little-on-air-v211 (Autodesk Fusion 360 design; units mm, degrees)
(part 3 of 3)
sketch "Broad XIAO short-end contact profile (3)" plane through (0, 0, -12.35) normal (0, 0, 1) x axis (1, 0, 0)
  line L1 (106.8, 55.8) -> (104.3, 55.8)
  line L2 (106.8, 58.2) -> (106.8, 55.8)
  line L3 (104.3, 58.2) -> (106.8, 58.2)
  line L4 (104.3, 55.8) -> (104.3, 58.2)
  point P2 (104.3, 55.8)
  point P3 (106.8, 55.8)
  point P4 (106.8, 58.2)
  dimension "d911" distance P2 P3 = 2.5
  dimension "d912" distance P3 P4 = 2.4
extrude "Extrude50" new body sketch "Broad XIAO short-end contact profile (3)" against normal blind 5.9 bodies "Broad XIAO short-end contact (3)"
combine "Combine3" bodies "Broad XIAO short-end contact", "Broad XIAO short-end contact (1)", "Broad XIAO short-end contact (2)", "Broad XIAO short-end contact (3)"
work_plane "WorkPlane51" AlongDistance -9.63 ExtraOffset 0
sketch "Reopen RGB sight through wide upper pad root profile" plane through (0, 0, -9.63) normal (0, 0, 1) x axis (1, 0, 0)
  circle C1 centre (103.605, 55.006) radius 1.6
  dimension "d917" diameter C1 = 3.2
extrude "Extrude51" cut sketch "Reopen RGB sight through wide upper pad root profile" against normal blind 8.9
work_plane "WorkPlane84" AlongDistance -9.48 ExtraOffset 0
sketch "Both MODE terminal rows load without a comb profile" plane through (0, 0, -9.48) normal (0, 0, 1) x axis (1, 0, 0)
  line L1 (63.1, 53.64) -> (56.9, 53.64)
  line L2 (63.1, 55.29) -> (63.1, 53.64)
  line L3 (56.9, 55.29) -> (63.1, 55.29)
  line L4 (56.9, 53.64) -> (56.9, 55.29)
  point P2 (56.9, 53.64)
  point P3 (63.1, 53.64)
  point P4 (63.1, 55.29)
  dimension "d922" distance P2 P3 = 6.2
  dimension "d923" distance P3 P4 = 1.65
extrude "Extrude84" cut sketch "Both MODE terminal rows load without a comb profile" against normal blind 8.57
work_plane "WorkPlane85" AlongDistance -9.48 ExtraOffset 0
sketch "POWER solder pins load from open front profile" plane through (0, 0, -9.48) normal (0, 0, 1) x axis (1, 0, 0)
  line L1 (46.1, 48.25) -> (35.9, 48.25)
  line L2 (46.1, 53.35) -> (46.1, 48.25)
  line L3 (35.9, 53.35) -> (46.1, 53.35)
  line L4 (35.9, 48.25) -> (35.9, 53.35)
  point P2 (35.9, 48.25)
  point P3 (46.1, 48.25)
  point P4 (46.1, 53.35)
  dimension "d928" distance P2 P3 = 10.2
  dimension "d929" distance P3 P4 = 5.1
extrude "Extrude85" cut sketch "POWER solder pins load from open front profile" against normal blind 11.02
work_plane "WorkPlane86" AlongDistance -9.48 ExtraOffset 0
sketch "XIAO keeper upper rail pocket profile" plane through (0, 0, -9.48) normal (0, 0, 1) x axis (1, 0, 0)
  line L1 (109.75, 57.35) -> (86.25, 57.35)
  line L2 (109.75, 58.05) -> (109.75, 57.35)
  line L3 (86.25, 58.05) -> (109.75, 58.05)
  line L4 (86.25, 57.35) -> (86.25, 58.05)
  point P2 (86.25, 57.35)
  point P3 (109.75, 57.35)
  point P4 (109.75, 58.05)
  dimension "d934" distance P2 P3 = 23.5
  dimension "d935" distance P3 P4 = 0.7
extrude "Extrude86" cut sketch "XIAO keeper upper rail pocket profile" against normal blind 3.17
work_plane "WorkPlane52" AlongDistance -9.63 ExtraOffset 0
sketch "Keeper clears upper-left closure boss profile" plane through (0, 0, -9.63) normal (0, 0, 1) x axis (1, 0, 0)
  line L1 (10.45, 49.55) -> (9.9, 49.55)
  line L2 (10.45, 58.45) -> (10.45, 49.55)
  line L3 (9.9, 58.45) -> (10.45, 58.45)
  line L4 (9.9, 49.55) -> (9.9, 58.45)
  point P2 (9.9, 49.55)
  point P3 (10.45, 49.55)
  point P4 (10.45, 58.45)
  dimension "d940" distance P2 P3 = 0.55
  dimension "d941" distance P3 P4 = 8.9
extrude "Extrude52" cut sketch "Keeper clears upper-left closure boss profile" against normal blind 5
work_plane "WorkPlane87" AlongDistance -9.48 ExtraOffset 0
sketch "Wide upper keeper landing clearance profile" plane through (0, 0, -9.48) normal (0, 0, 1) x axis (1, 0, 0)
  line L1 (91.05, 57.35) -> (88.15, 57.35)
  line L2 (91.05, 58.45) -> (91.05, 57.35)
  line L3 (88.15, 58.45) -> (91.05, 58.45)
  line L4 (88.15, 57.35) -> (88.15, 58.45)
  point P2 (88.15, 57.35)
  point P3 (91.05, 57.35)
  point P4 (91.05, 58.45)
  dimension "d946" distance P2 P3 = 2.9
  dimension "d947" distance P3 P4 = 1.1
extrude "Extrude87" cut sketch "Wide upper keeper landing clearance profile" against normal blind 9.02
work_plane "WorkPlane88" AlongDistance -9.48 ExtraOffset 0
sketch "Wide upper keeper landing clearance profile (1)" plane through (0, 0, -9.48) normal (0, 0, 1) x axis (1, 0, 0)
  line L1 (107.05, 57.35) -> (104.05, 57.35)
  line L2 (107.05, 58.45) -> (107.05, 57.35)
  line L3 (104.05, 58.45) -> (107.05, 58.45)
  line L4 (104.05, 57.35) -> (104.05, 58.45)
  point P2 (104.05, 57.35)
  point P3 (107.05, 57.35)
  point P4 (107.05, 58.45)
  dimension "d952" distance P2 P3 = 3
  dimension "d953" distance P3 P4 = 1.1
extrude "Extrude88" cut sketch "Wide upper keeper landing clearance profile (1)" against normal blind 9.02
work_plane "WorkPlane89" AlongDistance -9.48 ExtraOffset 0
sketch "Open POWER bracket ends without thin fins profile" plane through (0, 0, -9.48) normal (0, 0, 1) x axis (1, 0, 0)
  line L1 (51.11, 57.65) -> (30.89, 57.65)
  line L2 (51.11, 58.6) -> (51.11, 57.65)
  line L3 (30.89, 58.6) -> (51.11, 58.6)
  line L4 (30.89, 57.65) -> (30.89, 58.6)
  point P2 (30.89, 57.65)
  point P3 (51.11, 57.65)
  point P4 (51.11, 58.6)
  dimension "d958" distance P2 P3 = 20.22
  dimension "d959" distance P3 P4 = 0.95
extrude "Extrude89" cut sketch "Open POWER bracket ends without thin fins profile" against normal blind 10.77
work_plane "WorkPlane1" AlongDistance -6.6 ExtraOffset 0
sketch "Closure screw shaft profile" plane through (0, 0, -6.6) normal (0, 0, 1) x axis (1, 0, 0)
  circle C1 centre (6, 6) radius 1.5
  dimension "d964" diameter C1 = 3
extrude "Extrude1" new body sketch "Closure screw shaft profile" against normal blind 8 bodies "Closure screw shaft"
work_plane "WorkPlane2" AlongDistance -4.95 ExtraOffset 0
sketch "Closure screw head profile" plane through (0, 0, -4.95) normal (0, 0, 1) x axis (1, 0, 0)
  circle C1 centre (6, 6) radius 2.85
  dimension "d969" diameter C1 = 5.7
extrude "Extrude2" new body sketch "Closure screw head profile" against normal blind 1.65 bodies "Closure screw head"
work_plane "WorkPlane1" AlongDistance -11.6 ExtraOffset 0
sketch "Nut profile" plane through (0, 0, -11.6) normal (0, 0, 1) x axis (1, 0, 0)
  line L1 (7.5877, 8.75) -> (9.1754, 6)
  line L2 (4.4123, 8.75) -> (7.5877, 8.75)
  line L3 (2.8246, 6) -> (4.4123, 8.75)
  line L4 (4.4123, 3.25) -> (2.8246, 6)
  line L5 (7.5877, 3.25) -> (4.4123, 3.25)
  line L6 (9.1754, 6) -> (7.5877, 3.25)
extrude "Extrude1" new body sketch "Nut profile" against normal blind 2.4 bodies "M3 nut"
work_plane "WorkPlane2" AlongDistance -11.59 ExtraOffset 0
sketch "M3 threaded bore envelope profile" plane through (0, 0, -11.59) normal (0, 0, 1) x axis (1, 0, 0)
  circle C1 centre (6, 6) radius 1.505
  dimension "d978" diameter C1 = 3.01
extrude "Extrude2" cut sketch "M3 threaded bore envelope profile" against normal blind 2.42
work_plane "WorkPlane3" AlongDistance -6.6 ExtraOffset 0
sketch "Closure screw shaft profile (1)" plane through (0, 0, -6.6) normal (0, 0, 1) x axis (1, 0, 0)
  circle C1 centre (114, 6) radius 1.5
  dimension "d983" diameter C1 = 3
extrude "Extrude3" new body sketch "Closure screw shaft profile (1)" against normal blind 8 bodies "Closure screw shaft (1)"
work_plane "WorkPlane4" AlongDistance -4.95 ExtraOffset 0
sketch "Closure screw head profile (1)" plane through (0, 0, -4.95) normal (0, 0, 1) x axis (1, 0, 0)
  circle C1 centre (114, 6) radius 2.85
  dimension "d988" diameter C1 = 5.7
extrude "Extrude4" new body sketch "Closure screw head profile (1)" against normal blind 1.65 bodies "Closure screw head (1)"
work_plane "WorkPlane3" AlongDistance -11.6 ExtraOffset 0
sketch "Nut profile (1)" plane through (0, 0, -11.6) normal (0, 0, 1) x axis (1, 0, 0)
  line L1 (115.5877, 8.75) -> (117.1754, 6)
  line L2 (112.4123, 8.75) -> (115.5877, 8.75)
  line L3 (110.8246, 6) -> (112.4123, 8.75)
  line L4 (112.4123, 3.25) -> (110.8246, 6)
  line L5 (115.5877, 3.25) -> (112.4123, 3.25)
  line L6 (117.1754, 6) -> (115.5877, 3.25)
extrude "Extrude3" new body sketch "Nut profile (1)" against normal blind 2.4 bodies "M3 nut (1)"
work_plane "WorkPlane4" AlongDistance -11.59 ExtraOffset 0
sketch "M3 threaded bore envelope profile (1)" plane through (0, 0, -11.59) normal (0, 0, 1) x axis (1, 0, 0)
  circle C1 centre (114, 6) radius 1.505
  dimension "d997" diameter C1 = 3.01
extrude "Extrude4" cut sketch "M3 threaded bore envelope profile (1)" against normal blind 2.42
work_plane "WorkPlane5" AlongDistance -6.6 ExtraOffset 0
sketch "Closure screw shaft profile (2)" plane through (0, 0, -6.6) normal (0, 0, 1) x axis (1, 0, 0)
  circle C1 centre (6, 54) radius 1.5
  dimension "d1002" diameter C1 = 3
extrude "Extrude5" new body sketch "Closure screw shaft profile (2)" against normal blind 8 bodies "Closure screw shaft (2)"
work_plane "WorkPlane6" AlongDistance -4.95 ExtraOffset 0
sketch "Closure screw head profile (2)" plane through (0, 0, -4.95) normal (0, 0, 1) x axis (1, 0, 0)
  circle C1 centre (6, 54) radius 2.85
  dimension "d1007" diameter C1 = 5.7
extrude "Extrude6" new body sketch "Closure screw head profile (2)" against normal blind 1.65 bodies "Closure screw head (2)"
work_plane "WorkPlane5" AlongDistance -11.6 ExtraOffset 0
sketch "Nut profile (2)" plane through (0, 0, -11.6) normal (0, 0, 1) x axis (1, 0, 0)
  line L1 (3.25, 55.5877) -> (6, 57.1754)
  line L2 (3.25, 52.4123) -> (3.25, 55.5877)
  line L3 (6, 50.8246) -> (3.25, 52.4123)
  line L4 (8.75, 52.4123) -> (6, 50.8246)
  line L5 (8.75, 55.5877) -> (8.75, 52.4123)
  line L6 (6, 57.1754) -> (8.75, 55.5877)
extrude "Extrude5" new body sketch "Nut profile (2)" against normal blind 2.4 bodies "M3 nut (2)"
work_plane "WorkPlane6" AlongDistance -11.59 ExtraOffset 0
sketch "M3 threaded bore envelope profile (2)" plane through (0, 0, -11.59) normal (0, 0, 1) x axis (1, 0, 0)
  circle C1 centre (6, 54) radius 1.505
  dimension "d1016" diameter C1 = 3.01
extrude "Extrude6" cut sketch "M3 threaded bore envelope profile (2)" against normal blind 2.42
work_plane "WorkPlane7" AlongDistance -6.6 ExtraOffset 0
sketch "Closure screw shaft profile (3)" plane through (0, 0, -6.6) normal (0, 0, 1) x axis (1, 0, 0)
  circle C1 centre (114, 54) radius 1.5
  dimension "d1021" diameter C1 = 3
extrude "Extrude7" new body sketch "Closure screw shaft profile (3)" against normal blind 8 bodies "Closure screw shaft (3)"
work_plane "WorkPlane8" AlongDistance -4.95 ExtraOffset 0
sketch "Closure screw head profile (3)" plane through (0, 0, -4.95) normal (0, 0, 1) x axis (1, 0, 0)
  circle C1 centre (114, 54) radius 2.85
  dimension "d1026" diameter C1 = 5.7
extrude "Extrude8" new body sketch "Closure screw head profile (3)" against normal blind 1.65 bodies "Closure screw head (3)"
work_plane "WorkPlane7" AlongDistance -11.6 ExtraOffset 0
sketch "Nut profile (3)" plane through (0, 0, -11.6) normal (0, 0, 1) x axis (1, 0, 0)
  line L1 (115.5877, 56.75) -> (117.1754, 54)
  line L2 (112.4123, 56.75) -> (115.5877, 56.75)
  line L3 (110.8246, 54) -> (112.4123, 56.75)
  line L4 (112.4123, 51.25) -> (110.8246, 54)
  line L5 (115.5877, 51.25) -> (112.4123, 51.25)
  line L6 (117.1754, 54) -> (115.5877, 51.25)
extrude "Extrude7" new body sketch "Nut profile (3)" against normal blind 2.4 bodies "M3 nut (3)"
work_plane "WorkPlane8" AlongDistance -11.59 ExtraOffset 0
sketch "M3 threaded bore envelope profile (3)" plane through (0, 0, -11.59) normal (0, 0, 1) x axis (1, 0, 0)
  circle C1 centre (114, 54) radius 1.505
  dimension "d1035" diameter C1 = 3.01
extrude "Extrude8" cut sketch "M3 threaded bore envelope profile (3)" against normal blind 2.42
work_plane "WorkPlane9" AlongDistance -1.075 ExtraOffset 0
sketch "Optical screw shaft profile" plane through (0, 0, -1.075) normal (0, 0, 1) x axis (1, 0, 0)
  circle C1 centre (60, 6) radius 1.5
  dimension "d1040" diameter C1 = 3
extrude "Extrude9" new body sketch "Optical screw shaft profile" against normal blind 8 bodies "Optical screw shaft"
work_plane "WorkPlane10" AlongDistance -9.075 ExtraOffset 0
sketch "Optical screw head profile" plane through (0, 0, -9.075) normal (0, 0, 1) x axis (1, 0, 0)
  circle C1 centre (60, 6) radius 2.85
  dimension "d1045" diameter C1 = 5.7
extrude "Extrude10" new body sketch "Optical screw head profile" against normal blind 1.65 bodies "Optical screw head"
work_plane "WorkPlane9" AlongDistance -3.3 ExtraOffset 0
sketch "Nut profile (4)" plane through (0, 0, -3.3) normal (0, 0, 1) x axis (1, 0, 0)
  line L1 (61.5877, 8.75) -> (63.1754, 6)
  line L2 (58.4123, 8.75) -> (61.5877, 8.75)
  line L3 (56.8246, 6) -> (58.4123, 8.75)
  line L4 (58.4123, 3.25) -> (56.8246, 6)
  line L5 (61.5877, 3.25) -> (58.4123, 3.25)
  line L6 (63.1754, 6) -> (61.5877, 3.25)
extrude "Extrude9" new body sketch "Nut profile (4)" against normal blind 2.4 bodies "M3 nut (4)"
work_plane "WorkPlane10" AlongDistance -3.29 ExtraOffset 0
sketch "M3 threaded bore envelope profile (4)" plane through (0, 0, -3.29) normal (0, 0, 1) x axis (1, 0, 0)
  circle C1 centre (60, 6) radius 1.505
  dimension "d1054" diameter C1 = 3.01
extrude "Extrude10" cut sketch "M3 threaded bore envelope profile (4)" against normal blind 2.42
work_plane "WorkPlane11" AlongDistance -1.075 ExtraOffset 0
sketch "Optical screw shaft profile (1)" plane through (0, 0, -1.075) normal (0, 0, 1) x axis (1, 0, 0)
  circle C1 centre (60, 54) radius 1.5
  dimension "d1059" diameter C1 = 3
extrude "Extrude11" new body sketch "Optical screw shaft profile (1)" against normal blind 8 bodies "Optical screw shaft (1)"
work_plane "WorkPlane12" AlongDistance -9.075 ExtraOffset 0
sketch "Optical screw head profile (1)" plane through (0, 0, -9.075) normal (0, 0, 1) x axis (1, 0, 0)
  circle C1 centre (60, 54) radius 2.85
  dimension "d1064" diameter C1 = 5.7
extrude "Extrude12" new body sketch "Optical screw head profile (1)" against normal blind 1.65 bodies "Optical screw head (1)"
work_plane "WorkPlane11" AlongDistance -3.3 ExtraOffset 0
sketch "Nut profile (5)" plane through (0, 0, -3.3) normal (0, 0, 1) x axis (1, 0, 0)
  line L1 (61.5877, 56.75) -> (63.1754, 54)
  line L2 (58.4123, 56.75) -> (61.5877, 56.75)
  line L3 (56.8246, 54) -> (58.4123, 56.75)
  line L4 (58.4123, 51.25) -> (56.8246, 54)
  line L5 (61.5877, 51.25) -> (58.4123, 51.25)
  line L6 (63.1754, 54) -> (61.5877, 51.25)
extrude "Extrude11" new body sketch "Nut profile (5)" against normal blind 2.4 bodies "M3 nut (5)"
work_plane "WorkPlane12" AlongDistance -3.29 ExtraOffset 0
sketch "M3 threaded bore envelope profile (5)" plane through (0, 0, -3.29) normal (0, 0, 1) x axis (1, 0, 0)
  circle C1 centre (60, 54) radius 1.505
  dimension "d1073" diameter C1 = 3.01
extrude "Extrude12" cut sketch "M3 threaded bore envelope profile (5)" against normal blind 2.42
work_plane "WorkPlane13" AlongDistance -9.65 ExtraOffset 0
sketch "Keeper screw shaft profile" plane through (0, 0, -9.65) normal (0, 0, 1) x axis (1, 0, 0)
  circle C1 centre (35, 38) radius 1.5
  dimension "d1078" diameter C1 = 3
extrude "Extrude13" new body sketch "Keeper screw shaft profile" against normal blind 8 bodies "Keeper screw shaft"
work_plane "WorkPlane14" AlongDistance -8 ExtraOffset 0
sketch "Keeper screw head profile" plane through (0, 0, -8) normal (0, 0, 1) x axis (1, 0, 0)
  circle C1 centre (35, 38) radius 2.85
  dimension "d1083" diameter C1 = 5.7
extrude "Extrude14" new body sketch "Keeper screw head profile" against normal blind 1.65 bodies "Keeper screw head"
work_plane "WorkPlane13" AlongDistance -13.9 ExtraOffset 0
sketch "Nut profile (6)" plane through (0, 0, -13.9) normal (0, 0, 1) x axis (1, 0, 0)
  line L1 (36.5877, 40.75) -> (38.1754, 38)
  line L2 (33.4123, 40.75) -> (36.5877, 40.75)
  line L3 (31.8246, 38) -> (33.4123, 40.75)
  line L4 (33.4123, 35.25) -> (31.8246, 38)
  line L5 (36.5877, 35.25) -> (33.4123, 35.25)
  line L6 (38.1754, 38) -> (36.5877, 35.25)
extrude "Extrude13" new body sketch "Nut profile (6)" against normal blind 2.4 bodies "M3 nut (6)"
work_plane "WorkPlane14" AlongDistance -13.89 ExtraOffset 0
sketch "M3 threaded bore envelope profile (6)" plane through (0, 0, -13.89) normal (0, 0, 1) x axis (1, 0, 0)
  circle C1 centre (35, 38) radius 1.505
  dimension "d1092" diameter C1 = 3.01
extrude "Extrude14" cut sketch "M3 threaded bore envelope profile (6)" against normal blind 2.42
work_plane "WorkPlane15" AlongDistance -9.65 ExtraOffset 0
sketch "Keeper screw shaft profile (1)" plane through (0, 0, -9.65) normal (0, 0, 1) x axis (1, 0, 0)
  circle C1 centre (73, 38) radius 1.5
  dimension "d1097" diameter C1 = 3
extrude "Extrude15" new body sketch "Keeper screw shaft profile (1)" against normal blind 8 bodies "Keeper screw shaft (1)"
work_plane "WorkPlane16" AlongDistance -8 ExtraOffset 0
sketch "Keeper screw head profile (1)" plane through (0, 0, -8) normal (0, 0, 1) x axis (1, 0, 0)
  circle C1 centre (73, 38) radius 2.85
  dimension "d1102" diameter C1 = 5.7
extrude "Extrude16" new body sketch "Keeper screw head profile (1)" against normal blind 1.65 bodies "Keeper screw head (1)"
work_plane "WorkPlane15" AlongDistance -13.9 ExtraOffset 0
sketch "Nut profile (7)" plane through (0, 0, -13.9) normal (0, 0, 1) x axis (1, 0, 0)
  line L1 (74.5877, 40.75) -> (76.1754, 38)
  line L2 (71.4123, 40.75) -> (74.5877, 40.75)
  line L3 (69.8246, 38) -> (71.4123, 40.75)
  line L4 (71.4123, 35.25) -> (69.8246, 38)
  line L5 (74.5877, 35.25) -> (71.4123, 35.25)
  line L6 (76.1754, 38) -> (74.5877, 35.25)
extrude "Extrude15" new body sketch "Nut profile (7)" against normal blind 2.4 bodies "M3 nut (7)"
work_plane "WorkPlane16" AlongDistance -13.89 ExtraOffset 0
sketch "M3 threaded bore envelope profile (7)" plane through (0, 0, -13.89) normal (0, 0, 1) x axis (1, 0, 0)
  circle C1 centre (73, 38) radius 1.505
  dimension "d1111" diameter C1 = 3.01
extrude "Extrude16" cut sketch "M3 threaded bore envelope profile (7)" against normal blind 2.42
work_plane "WorkPlane53" AlongDistance -9.63 ExtraOffset 0
sketch "Optical head running pocket with thick roof profile" plane through (0, 0, -9.63) normal (0, 0, 1) x axis (1, 0, 0)
  circle C1 centre (60, 54) radius 3.2
  dimension "d1116" diameter C1 = 6.4
extrude "Extrude53" cut sketch "Optical head running pocket with thick roof profile" against normal blind 1.5
work_plane "WorkPlane90" AlongDistance -13.8 ExtraOffset 0
sketch "Keeper nut clears later charger fence" plane through (0, 0, -13.8) normal (0, 0, 1) x axis (1, 0, 0)
  line L1 (36.7321, 41) -> (38.4641, 38)
  line L2 (33.2679, 41) -> (36.7321, 41)
  line L3 (31.5359, 38) -> (33.2679, 41)
  line L4 (33.2679, 35) -> (31.5359, 38)
  line L5 (36.7321, 35) -> (33.2679, 35)
  line L6 (38.4641, 38) -> (36.7321, 35)
extrude "Extrude90" cut sketch "Keeper nut clears later charger fence" against normal blind 3
work_plane "WorkPlane91" AlongDistance -15 ExtraOffset 0
sketch "Full 17.5 mm charger lower edge stop profile" plane through (0, 0, -15) normal (0, 0, 1) x axis (1, 0, 0)
  line L1 (29.75, 28.1) -> (12.25, 28.1)
  line L2 (29.75, 30) -> (29.75, 28.1)
  line L3 (12.25, 30) -> (29.75, 30)
  line L4 (12.25, 28.1) -> (12.25, 30)
  point P2 (12.25, 28.1)
  point P3 (29.75, 28.1)
  point P4 (29.75, 30)
  dimension "d1125" distance P2 P3 = 17.5
  dimension "d1126" distance P3 P4 = 1.9
extrude "Extrude91" new body sketch "Full 17.5 mm charger lower edge stop profile" against normal blind 6.7 bodies "Full 17.5 mm charger lower edge stop"
combine "Combine8" bodies "Full 17.5 mm charger lower edge stop"
work_plane "WorkPlane1" AlongDistance 0.8 ExtraOffset 0
sketch "Optical shaft profile" plane through (0, 0, 0.8) normal (0, 0, 1) x axis (1, 0, 0)
  circle C1 centre (103.605, 55.006) radius 1.525
  dimension "d1132" diameter C1 = 3.05 (= "indicator_guide_diameter")
extrude "Extrude1" new body sketch "Optical shaft profile" against normal blind 15.5 bodies "Optical shaft"
work_plane "WorkPlane2" AlongDistance -14.65 ExtraOffset 0
sketch "Narrow 1.8 mm LED pickup clears USB metal profile" plane through (0, 0, -14.65) normal (0, 0, 1) x axis (1, 0, 0)
  circle C1 centre (103.605, 55.006) radius 0.9
  dimension "d1137" diameter C1 = 1.8
extrude "Extrude2" new body sketch "Narrow 1.8 mm LED pickup clears USB metal profile" against normal blind 2.85 bodies "Narrow 1.8 mm LED pickup clears USB metal"
work_plane "WorkPlane3" AlongDistance 0.8 ExtraOffset 0
sketch "Insertion stop collar profile" plane through (0, 0, 0.8) normal (0, 0, 1) x axis (1, 0, 0)
  circle C1 centre (103.605, 55.006) radius 2.1
  dimension "d1142" diameter C1 = 4.2
extrude "Extrude3" new body sketch "Insertion stop collar profile" against normal blind 0.8 bodies "Insertion stop collar"
combine "Combine1" bodies "Narrow 1.8 mm LED pickup clears USB metal", "Insertion stop collar"
work_plane "WorkPlane4" AlongDistance 0.81 ExtraOffset 0
sketch "Continuous flat printing face profile" plane through (0, 0, 0.81) normal (0, 0, 1) x axis (1, 0, 0)
  line L1 (106.605, 51.006) -> (100.605, 51.006)
  line L2 (106.605, 54.306) -> (106.605, 51.006)
  line L3 (100.605, 54.306) -> (106.605, 54.306)
  line L4 (100.605, 51.006) -> (100.605, 54.306)
  point P2 (100.605, 51.006)
  point P3 (106.605, 51.006)
  point P4 (106.605, 54.306)
  dimension "d1147" distance P2 P3 = 6
  dimension "d1148" distance P3 P4 = 3.3
extrude "Extrude4" cut sketch "Continuous flat printing face profile" against normal blind 18.32
work_plane "WorkPlane1" AlongDistance -17.6 ExtraOffset 0
sketch "Optical shaft profile" plane through (0, 0, -17.6) normal (0, 0, 1) x axis (1, 0, 0)
  circle C1 centre (14, 49.4) radius 1.525
  dimension "d1153" diameter C1 = 3.05 (= "indicator_guide_diameter")
extrude "Extrude1" new body sketch "Optical shaft profile" against normal blind 6.3 bodies "Optical shaft"
work_plane "WorkPlane2" AlongDistance -20.5 ExtraOffset 0
sketch "Insertion stop collar profile" plane through (0, 0, -20.5) normal (0, 0, 1) x axis (1, 0, 0)
  circle C1 centre (14, 49.4) radius 2.1
  dimension "d1158" diameter C1 = 4.2
extrude "Extrude2" new body sketch "Insertion stop collar profile" against normal blind 1.2 bodies "Insertion stop collar"
combine "Combine1" bodies "Insertion stop collar"
work_plane "WorkPlane3" AlongDistance -17.59 ExtraOffset 0
sketch "Continuous flat printing face profile" plane through (0, 0, -17.59) normal (0, 0, 1) x axis (1, 0, 0)
  line L1 (17, 45.4) -> (11, 45.4)
  line L2 (17, 48.7) -> (17, 45.4)
  line L3 (11, 48.7) -> (17, 48.7)
  line L4 (11, 45.4) -> (11, 48.7)
  point P2 (11, 45.4)
  point P3 (17, 45.4)
  point P4 (17, 48.7)
  dimension "d1163" distance P2 P3 = 6
  dimension "d1164" distance P3 P4 = 3.3
extrude "Extrude3" cut sketch "Continuous flat printing face profile" against normal blind 6.32
work_plane "WorkPlane4" AlongDistance -17.59 ExtraOffset 0
sketch "Charger fence relief flat profile" plane through (0, 0, -17.59) normal (0, 0, 1) x axis (1, 0, 0)
  line L1 (12.2, 46.4) -> (11, 46.4)
  line L2 (12.2, 52.4) -> (12.2, 46.4)
  line L3 (11, 52.4) -> (12.2, 52.4)
  line L4 (11, 46.4) -> (11, 52.4)
  point P2 (11, 46.4)
  point P3 (12.2, 46.4)
  point P4 (12.2, 52.4)
  dimension "d1169" distance P2 P3 = 1.2
  dimension "d1170" distance P3 P4 = 6
extrude "Extrude4" cut sketch "Charger fence relief flat profile" against normal blind 6.32
work_plane "WorkPlane1" AlongDistance -17.6 ExtraOffset 0
sketch "Optical shaft profile" plane through (0, 0, -17.6) normal (0, 0, 1) x axis (1, 0, 0)
  circle C1 centre (14, 44.65) radius 1.525
  dimension "d1175" diameter C1 = 3.05 (= "indicator_guide_diameter")
extrude "Extrude1" new body sketch "Optical shaft profile" against normal blind 6.3 bodies "Optical shaft"
work_plane "WorkPlane2" AlongDistance -20.5 ExtraOffset 0
sketch "Insertion stop collar profile" plane through (0, 0, -20.5) normal (0, 0, 1) x axis (1, 0, 0)
  circle C1 centre (14, 44.65) radius 2.1
  dimension "d1180" diameter C1 = 4.2
extrude "Extrude2" new body sketch "Insertion stop collar profile" against normal blind 1.2 bodies "Insertion stop collar"
combine "Combine1" bodies "Insertion stop collar"
work_plane "WorkPlane3" AlongDistance -17.59 ExtraOffset 0
sketch "Continuous flat printing face profile" plane through (0, 0, -17.59) normal (0, 0, 1) x axis (1, 0, 0)
  line L1 (17, 40.65) -> (11, 40.65)
  line L2 (17, 43.95) -> (17, 40.65)
  line L3 (11, 43.95) -> (17, 43.95)
  line L4 (11, 40.65) -> (11, 43.95)
  point P2 (11, 40.65)
  point P3 (17, 40.65)
  point P4 (17, 43.95)
  dimension "d1185" distance P2 P3 = 6
  dimension "d1186" distance P3 P4 = 3.3
extrude "Extrude3" cut sketch "Continuous flat printing face profile" against normal blind 6.32
work_plane "WorkPlane4" AlongDistance -17.59 ExtraOffset 0
sketch "Charger fence relief flat profile" plane through (0, 0, -17.59) normal (0, 0, 1) x axis (1, 0, 0)
  line L1 (12.2, 41.65) -> (11, 41.65)
  line L2 (12.2, 47.65) -> (12.2, 41.65)
  line L3 (11, 47.65) -> (12.2, 47.65)
  line L4 (11, 41.65) -> (11, 47.65)
  point P2 (11, 41.65)
  point P3 (12.2, 41.65)
  point P4 (12.2, 47.65)
  dimension "d1191" distance P2 P3 = 1.2
  dimension "d1192" distance P3 P4 = 6
extrude "Extrude4" cut sketch "Charger fence relief flat profile" against normal blind 6.32
chamfer "Chamfer1" distance 1.4 (= "front_outer_bevel") bodies "Body1"
chamfer "Chamfer2" distance 0.8 (= "front_opening_bevel") bodies "Body1"
extrude "Extrude11" new body of existing geometry blind 0.35
combine "Combine4" sketch "Front reset guide broad collar profile"
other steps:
create_component "CreateComponent1"
create_component "CreateComponent2"
create_component "CreateComponent3"
create_component "CreateComponent4"
create_component "CreateComponent5"
create_component "CreateComponent6"
create_component "CreateComponent7"
create_component "CreateComponent8"
create_component "CreateComponent9"
create_component "CreateComponent10"
create_component "CreateComponent11"
create_component "CreateComponent12"
create_component "CreateComponent13"
create_component "CreateComponent14"
create_component "CreateComponent15"
create_component "CreateComponent16"
create_component "CreateComponent17"
create_component "CreateComponent18"
create_component "CreateComponent19"
create_component "CreateComponent20"
create_component "CreateComponent21"
create_component "CreateComponent22"
create_component "CreateComponent23"
named bodies: "Body1", "LED module", "LED module (1)", "LED module (2)", "LED module (3)", "Charger PCB", "Charger IC envelope", "Measured USB-C socket envelope", "Measured charger indicator", "Measured charger indicator (1)", "SPDT main body", "SPDT lever", "Measured DPDT body", "Measured 0.7 mm terminal", "Measured 0.7 mm terminal (1)", "Measured 0.7 mm terminal (2)", "Measured 0.7 mm terminal (3)", "Measured 0.7 mm terminal (4)", "Measured 0.7 mm terminal (5)", "Direct MODE actuator", "XIAO PCB", "XIAO component envelope", "Measured centered USB-C socket", "Measured reset target 1.8 mm from PCB back", "RGB6 status LED manufacturer position", "Close obsolete upper-right screw opening", "New upper-right corner compression seat", "Front reset guide broad collar", "Slim rear envelope", "Closure boss", "Keeper boss", "Battery low fence", "Battery low fence (1)", "Battery low fence (2)", "Battery low fence (3)", "Battery insulated bed", "Strap lug", "Strap lug (1)", "Charger clear-area PCB seat", "Charger clear-area PCB seat (1)", "Charger clear-area PCB seat (2)", "Charger clear-area PCB seat (3)", "Charger side fence", "Charger side fence (1)", "Charger lower central stop", "Charger upper end stop", "Charger upper end stop (1)", "XIAO short-end PCB seat", "XIAO short-end PCB seat (1)", "XIAO short-end PCB seat (2)", "XIAO short-end PCB seat (3)", "XIAO reset reaction support", "XIAO bottom end stop", "XIAO upper end stop", "XIAO upper end stop (1)", "XIAO short corner lateral stop", "XIAO short corner lateral stop (1)", "XIAO short corner lateral stop (2)", "XIAO short corner lateral stop (3)", "POWER nest"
